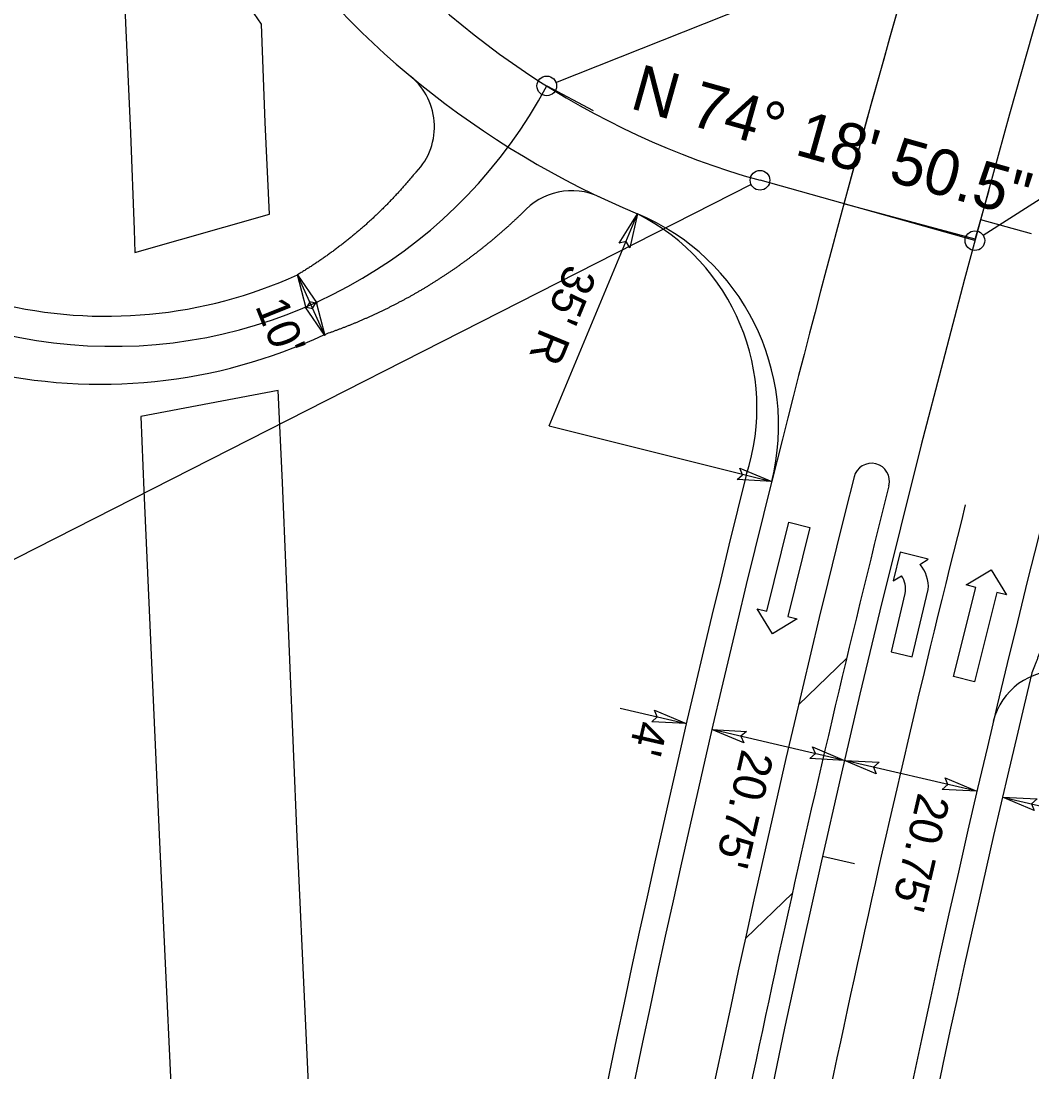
# Model space of a CAD drawing. Extents: x 1778969 to 1790720, y 807089 to 817794.
# Drawn here: x 1780913.9 to 1781068, y 812006.4 to 812166.6 of the extents above; entities that cross this region are included whole.
import ezdxf

# ---------------------------------------------------------------- set-up
doc = ezdxf.new("R2010")
doc.units = 0
for name, color, linetype in [('Prop Dimension', 7, 'Continuous'), ('Prop Dimension Text', 7, 'Continuous'), ('Prop EOT', 7, 'Continuous'), ('Prop Hatching', 7, 'Continuous'), ('Prop Horizontal Alignment', 7, 'Continuous'), ('Prop Horizontal Alignment Direction Label', 7, 'Continuous'), ('Prop Horizontal Alignment Station Label', 7, 'Continuous'), ('Prop Horizontal Alignment Tick Large', 7, 'Continuous'), ('Prop Horizontal Alignment Tick Small', 7, 'Continuous'), ('Prop Lane Arrow CELL', 7, 'Continuous'), ('Prop Lane Lines', 7, 'Continuous'), ('Prop Paved Shoulder', 7, 'Continuous'), ('Prop Rem of Exist Asph Pvmt', 7, 'Continuous'), ('Prop Terminator CELL', 7, 'Continuous'), ('Scratch_Level_2', 7, 'Continuous'), ('Scratch_Level_3', 7, 'Continuous')]:
    doc.layers.add(name, color=color, linetype=linetype)

msp = doc.modelspace()

# ---------------------------------------------------------------- linework, layer by layer
at = {"layer": 'Prop Dimension'}
for p, q in [((1780994.37, 812104.92), (1781007.87, 812137.21)), ((1780960.19, 812118.66), (1780956.01, 812127.94)), ((1780994.37, 812104.92), (1781028.32, 812096.43)), ((1781005.22, 812061.87), (1781015.3, 812059.53)), ((1781039.41, 812053.92), (1781019.2, 812058.62)), ((1781059.62, 812049.22), (1781039.41, 812053.92)), ((1781063.52, 812048.31), (1781074.79, 812045.69))]:
    msp.add_line(p, q, dxfattribs=at)
at = {"layer": 'Prop EOT'}
for centre, radius, start, end in [((1783308.81, 811525.98), 2309.25, 153.74801, 174.52695), ((1781060.34, 812262.68), 136, 182.6702, 247.3077), ((1780966.9, 812150.5), 10, 313.2523, 50.2067), ((1780997.81, 812130.75), 10, 64.64, 138.7935), ((1780994.37, 812104.92), 35, 345.956, 67.3077), ((1780926.89, 812191.94), 70.32, 256.2726, 294.4698), ((1780926, 812191.87), 80.62, 256.7781, 294.9753), ((1783308.81, 811525.98), 2350.75, 165.94828, 174.52695), ((1781071.84, 812057.52), 10, 85.109, 166.6335)]:
    msp.add_arc(centre, radius, start, end, dxfattribs=at)
for points in [[(1780973.75, 812143.22), (1780973.55, 812142.98), (1780973.35, 812142.74), (1780973.15, 812142.5), (1780972.95, 812142.26), (1780972.75, 812142.02), (1780972.54, 812141.79), (1780972.34, 812141.55), (1780972.13, 812141.32), (1780971.93, 812141.08), (1780971.72, 812140.85), (1780971.51, 812140.62), (1780971.3, 812140.39), (1780971.08, 812140.15), (1780970.87, 812139.93), (1780970.66, 812139.7), (1780970.44, 812139.47), (1780970.22, 812139.24), (1780970.01, 812139.01), (1780969.79, 812138.79), (1780969.57, 812138.56), (1780969.34, 812138.34), (1780969.12, 812138.12), (1780968.9, 812137.9), (1780968.67, 812137.68), (1780968.45, 812137.46), (1780968.22, 812137.24), (1780967.99, 812137.02), (1780967.76, 812136.8), (1780967.53, 812136.59), (1780967.3, 812136.37), (1780967.06, 812136.16), (1780966.83, 812135.94), (1780966.59, 812135.73), (1780966.36, 812135.52), (1780966.12, 812135.31), (1780965.88, 812135.1), (1780965.64, 812134.89), (1780965.4, 812134.68), (1780965.16, 812134.48), (1780964.91, 812134.27), (1780964.67, 812134.07), (1780964.42, 812133.86), (1780964.18, 812133.66), (1780963.93, 812133.46), (1780963.68, 812133.26), (1780963.43, 812133.06), (1780963.18, 812132.86), (1780962.93, 812132.67), (1780962.67, 812132.47), (1780962.42, 812132.28), (1780962.16, 812132.08), (1780961.91, 812131.89), (1780961.65, 812131.7), (1780961.39, 812131.51), (1780961.13, 812131.32), (1780960.87, 812131.13), (1780960.61, 812130.94), (1780960.35, 812130.76), (1780960.08, 812130.57), (1780959.82, 812130.39), (1780959.55, 812130.21), (1780959.29, 812130.02), (1780959.02, 812129.84), (1780958.75, 812129.66), (1780958.48, 812129.49), (1780958.21, 812129.31), (1780957.94, 812129.13), (1780957.67, 812128.96), (1780957.39, 812128.79), (1780957.12, 812128.61), (1780956.84, 812128.44), (1780956.57, 812128.27), (1780956.01, 812127.94)], [(1780990.28, 812137.34), (1780989.93, 812136.99), (1780989.57, 812136.66), (1780989.21, 812136.32), (1780988.85, 812135.99), (1780988.49, 812135.65), (1780988.13, 812135.32), (1780987.76, 812135), (1780987.39, 812134.67), (1780987.02, 812134.35), (1780986.65, 812134.03), (1780986.28, 812133.71), (1780985.91, 812133.39), (1780985.53, 812133.08), (1780985.15, 812132.77), (1780984.77, 812132.46), (1780984.39, 812132.16), (1780984.01, 812131.85), (1780983.63, 812131.55), (1780983.24, 812131.25), (1780982.85, 812130.96), (1780982.46, 812130.66), (1780982.07, 812130.37), (1780981.68, 812130.08), (1780981.29, 812129.8), (1780980.89, 812129.51), (1780980.5, 812129.23), (1780980.1, 812128.95), (1780979.7, 812128.68), (1780979.3, 812128.4), (1780978.9, 812128.13), (1780978.49, 812127.86), (1780978.09, 812127.6), (1780977.68, 812127.33), (1780977.28, 812127.07), (1780976.87, 812126.81), (1780976.46, 812126.56), (1780976.04, 812126.3), (1780975.63, 812126.05), (1780975.22, 812125.8), (1780974.8, 812125.56), (1780974.38, 812125.31), (1780973.97, 812125.07), (1780973.55, 812124.84), (1780973.13, 812124.6), (1780972.71, 812124.37), (1780972.28, 812124.14), (1780971.86, 812123.91), (1780971.43, 812123.69), (1780971.01, 812123.46), (1780970.58, 812123.24), (1780970.15, 812123.03), (1780969.72, 812122.81), (1780969.29, 812122.6), (1780968.86, 812122.39), (1780968.43, 812122.19), (1780967.99, 812121.98), (1780967.56, 812121.78), (1780967.12, 812121.58), (1780966.69, 812121.39), (1780966.25, 812121.2), (1780965.81, 812121.01), (1780965.37, 812120.82), (1780964.93, 812120.63), (1780964.49, 812120.45), (1780964.05, 812120.27), (1780963.61, 812120.1), (1780963.16, 812119.92), (1780962.72, 812119.75), (1780962.27, 812119.58), (1780961.83, 812119.42), (1780961.38, 812119.25), (1780960.93, 812119.09), (1780960.04, 812118.78)]]:
    msp.add_spline(points, degree=3, dxfattribs=at)
at = {"layer": 'Prop Hatching'}
for p, q in [((1781039.74, 812069.46), (1781032.4, 812062.38)), ((1781031.47, 812033.69), (1781024.31, 812026.78))]:
    msp.add_line(p, q, dxfattribs=at)
at = {"layer": 'Prop Horizontal Alignment'}
msp.add_line((1781059.31, 812133.14), (1781026.54, 812142.34), dxfattribs=at)
for centre, radius, start, end in [((1783308.81, 811525.98), 2330, 144.08998, 185.35942), ((1781060.34, 812262.68), 125, 182.6702, 254.314), ((1780927.84, 812192.02), 75, 206.2323, 331.9308)]:
    msp.add_arc(centre, radius, start, end, dxfattribs=at)
at = {"layer": 'Prop Horizontal Alignment Station Label'}
for p, q in [((1780995.43, 812157.24), (1781168.41, 812226.38)), ((1781060.57, 812133.95), (1781190.63, 812217.49)), ((1781025.18, 812141.72), (1780895.08, 812075.57))]:
    msp.add_line(p, q, dxfattribs=at)
for centre in [(1780994.02, 812156.73), (1781026.54, 812142.34), (1781059.31, 812133.14)]:
    msp.add_circle(centre, 1.5, dxfattribs=at)
at = {"layer": 'Prop Horizontal Alignment Tick Large'}
for p, q in [((1780994.02, 812156.73), (1781001.08, 812152.96)), ((1781059.31, 812133.14), (1781061.47, 812140.84)), ((1781060.17, 812136.34), (1781067.9, 812134.24))]:
    msp.add_line(p, q, dxfattribs=at)
at = {"layer": 'Prop Horizontal Alignment Tick Small'}
msp.add_line((1781036.06, 812039.3), (1781040.93, 812038.2), dxfattribs=at)
at = {"layer": 'Prop Lane Arrow CELL'}
for p, q in [((1781027.56, 812076.65), (1781030.96, 812090.23)), ((1781034.16, 812089.43), (1781030.76, 812075.85)), ((1781030.96, 812090.23), (1781034.16, 812089.43)), ((1781047.91, 812085.63), (1781046.83, 812081.26)), ((1781052.18, 812084.57), (1781047.91, 812085.63)), ((1781050.92, 812083.79), (1781052.18, 812084.57)), ((1781058, 812080.66), (1781061.77, 812082.96)), ((1781061.77, 812082.96), (1781064.11, 812079.13)), ((1781046.83, 812081.26), (1781048.09, 812082.04)), ((1781049.76, 812069.68), (1781052.18, 812079.95)), ((1781056.05, 812066.71), (1781059.46, 812080.29)), ((1781059.46, 812080.29), (1781058, 812080.66)), ((1781048.64, 812079.34), (1781046.55, 812070.44)), ((1781062.66, 812079.49), (1781059.26, 812065.91)), ((1781064.11, 812079.13), (1781062.66, 812079.49)), ((1781028.45, 812073.18), (1781026.11, 812077.01)), ((1781026.11, 812077.01), (1781027.56, 812076.65)), ((1781032.22, 812075.48), (1781028.45, 812073.18)), ((1781030.76, 812075.85), (1781032.22, 812075.48)), ((1781046.55, 812070.44), (1781049.76, 812069.68)), ((1781059.26, 812065.91), (1781056.05, 812066.71))]:
    msp.add_line(p, q, dxfattribs=at)
for centre, radius, start, end in [((1781046.96, 812080.37), 5.25, 355.4462, 40.7579), ((1781045.47, 812080.1), 3.27, 346.7701, 36.4283)]:
    msp.add_arc(centre, radius, start, end, dxfattribs=at)
at = {"layer": 'Prop Lane Lines'}
for centre, radius, start, end in [((1781043.54, 812096.45), 2.75, 345.7973, 165.7973), ((1783308.81, 811525.98), 2338.75, 165.86471, 174.52217), ((1783308.81, 811525.98), 2333.25, 165.86487, 169.48591), ((1783308.81, 811525.98), 2321.25, 165.86487, 169.77028)]:
    msp.add_arc(centre, radius, start, end, dxfattribs=at)
at = {"layer": 'Prop Paved Shoulder'}
for centre, radius, start, end in [((1780992.99, 812107.66), 33.08, 341.9222, 63.2738), ((1783308.81, 811525.98), 2354.75, 165.95604, 174.52695), ((1783308.81, 811525.98), 2305.25, 166.41947, 174.52695)]:
    msp.add_arc(centre, radius, start, end, dxfattribs=at)
msp.add_spline([(1781082.47, 812104.41), (1781082.27, 812103.91), (1781082.07, 812103.41), (1781081.88, 812102.91), (1781081.68, 812102.41), (1781081.48, 812101.91), (1781081.28, 812101.41), (1781081.08, 812100.91), (1781080.88, 812100.41), (1781080.68, 812099.91), (1781080.48, 812099.41), (1781080.29, 812098.91), (1781080.09, 812098.41), (1781079.89, 812097.91), (1781079.69, 812097.41), (1781079.49, 812096.91), (1781079.29, 812096.41), (1781079.1, 812095.91), (1781078.9, 812095.41), (1781078.7, 812094.91), (1781078.5, 812094.4), (1781078.31, 812093.9), (1781078.11, 812093.4), (1781077.91, 812092.9), (1781077.72, 812092.4), (1781077.52, 812091.9), (1781077.32, 812091.4), (1781077.13, 812090.9), (1781076.93, 812090.4), (1781076.73, 812089.9), (1781076.54, 812089.39), (1781076.34, 812088.89), (1781076.14, 812088.39), (1781075.95, 812087.89), (1781075.75, 812087.39), (1781075.56, 812086.89), (1781075.36, 812086.39), (1781075.17, 812085.88), (1781074.97, 812085.38), (1781074.78, 812084.88), (1781074.58, 812084.38), (1781074.38, 812083.88), (1781074.19, 812083.37), (1781074, 812082.87), (1781073.8, 812082.37), (1781073.61, 812081.87), (1781073.41, 812081.37), (1781073.22, 812080.86), (1781073.02, 812080.36), (1781072.83, 812079.86), (1781072.63, 812079.36), (1781072.44, 812078.85), (1781072.25, 812078.35), (1781072.05, 812077.85), (1781071.86, 812077.35), (1781071.67, 812076.84), (1781071.47, 812076.34), (1781071.28, 812075.84), (1781071.09, 812075.33), (1781070.89, 812074.83), (1781070.7, 812074.33), (1781070.51, 812073.82), (1781070.32, 812073.32), (1781070.12, 812072.82), (1781069.93, 812072.31), (1781069.74, 812071.81), (1781069.55, 812071.31), (1781069.35, 812070.8), (1781069.16, 812070.3), (1781068.97, 812069.8), (1781068.78, 812069.29), (1781068.59, 812068.79), (1781068.39, 812068.29), (1781068.01, 812067.28)], degree=3, dxfattribs=at)
at = {"layer": 'Prop Rem of Exist Asph Pvmt'}
for p, q in [((1780950.52, 812166.14), (1780928.32, 812198.92)), ((1780931.23, 812131.33), (1780951.75, 812137.16)), ((1780953.05, 812110.3), (1780932.15, 812106.31))]:
    msp.add_line(p, q, dxfattribs=at)
for points in [[(1780928.32, 812198.92), (1780930.56, 812149.53), (1780931.1, 812134.79), (1780931.23, 812131.33)], [(1780951.75, 812137.16), (1780951.08, 812151.14), (1780950.52, 812166.14)], [(1780960.74, 811938.54), (1780958.5, 811986.92), (1780955.97, 812042.2), (1780953.72, 812096.29), (1780953.05, 812110.3)], [(1780932.15, 812106.31), (1780932.57, 812095.06), (1780934.95, 812041.44), (1780937.57, 811986.07), (1780939.66, 811936.25)]]:
    msp.add_lwpolyline(points, dxfattribs=at)
at = {"layer": 'Prop Terminator CELL'}
for points in [[(1781005.05, 812132.77), (1781007.87, 812137.21), (1781006.71, 812132.04), (1781006.12, 812133.01)], [(1780957.33, 812122.84), (1780956.01, 812127.94), (1780958.99, 812123.56), (1780957.88, 812123.79)], [(1780958.88, 812123.75), (1780960.19, 812118.66), (1780957.21, 812123.03), (1780958.32, 812122.81)], [(1781023.48, 812098.47), (1781028.32, 812096.43), (1781023.04, 812096.71), (1781023.89, 812097.46)], [(1781010.46, 812061.57), (1781015.3, 812059.53), (1781010.02, 812059.81), (1781010.87, 812060.56)], [(1781024.05, 812056.58), (1781019.2, 812058.62), (1781024.48, 812058.34), (1781023.63, 812057.59)], [(1781034.56, 812055.96), (1781039.41, 812053.92), (1781034.12, 812054.2), (1781034.98, 812054.95)], [(1781044.26, 812051.88), (1781039.41, 812053.92), (1781044.7, 812053.64), (1781043.84, 812052.89)], [(1781054.77, 812051.26), (1781059.62, 812049.22), (1781054.33, 812049.5), (1781055.19, 812050.25)], [(1781068.36, 812046.27), (1781063.52, 812048.31), (1781068.8, 812048.03), (1781067.95, 812047.28)]]:
    msp.add_lwpolyline(points, close=True, dxfattribs=at)
at = {"layer": 'Scratch_Level_2'}
msp.add_arc((1783308.81, 811525.98), 2350.75, 163.35801, 165.95604, dxfattribs=at)
at = {"layer": 'Scratch_Level_3'}
msp.add_line((1781059.36, 812133.34), (1781039.33, 812138.75), dxfattribs=at)
msp.add_arc((1783308.81, 811525.98), 2350.75, 144.08998, 164.89021, dxfattribs=at)

# ---------------------------------------------------------------- texts
at = {"layer": 'Prop Dimension Text'}
for s, rotation, p in [("35' R", 247.6246, (1780997.11, 812129.78)), ("10'", 291.8341, (1780949.51, 812123.19)), ("4'", 256.9847, (1781007.61, 812060.18)), ("20.75'", 256.9072, (1781023.79, 812055.78)), ("20.75'", 256.9072, (1781050.67, 812049.14))]:
    msp.add_text(s, height=5, rotation=rotation, dxfattribs=at).set_placement(p)
at = {"layer": 'Prop Horizontal Alignment Direction Label'}
msp.add_text('N 74%%d 18\' 50.5" W', height=7, rotation=344.314, dxfattribs=at).set_placement((1781006.52, 812153.37))

doc.saveas('drawing.dxf')
